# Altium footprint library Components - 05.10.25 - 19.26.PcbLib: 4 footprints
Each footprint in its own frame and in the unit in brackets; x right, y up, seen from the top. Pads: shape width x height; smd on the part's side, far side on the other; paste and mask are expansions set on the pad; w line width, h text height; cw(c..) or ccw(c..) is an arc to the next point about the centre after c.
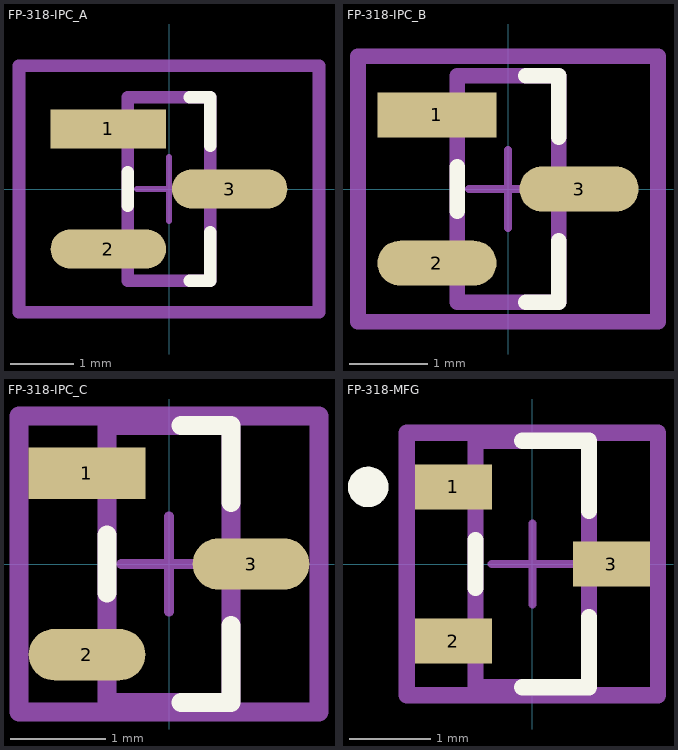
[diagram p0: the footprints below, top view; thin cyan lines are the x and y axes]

## FP-318-IPC_A [mm]
pads (3):
  rect 1.824x0.618 smd paste+0 mask+0: 1(-0.96,0.95)
  rrect100% 1.824x0.618 smd paste+0 mask+0: 2(-0.96,-0.95) 3(0.96,0)
Top Overlay:
  lines w0.2: -0.65,-0.266 -0.65,0.266 ; 0.327,-1.45 0.65,-1.45 0.65,-0.684 ; 0.327,1.45 0.65,1.45 0.65,0.684
Top Assembly:
  lines w0.2: -2.372,-1.95 2.372,-1.95 2.372,1.95 -2.372,1.95 -2.372,-1.95
  text ".Designator" at 0,0 h1
Top 3D Body:
  lines w0.2: -0.65,-1.45 0.65,-1.45 0.65,1.45 -0.65,1.45 -0.65,-1.45
Top Courtyard:
  lines w0.2: -2.372,-1.95 2.372,-1.95 2.372,1.95 -2.372,1.95 -2.372,-1.95
Top Component Center:
  lines w0.1: -0.5,0 0.5,0 ; 0,-0.5 0,0.5
3D body "Trans_onsemi_MMBT5179_eec.STEP": height 0.25, standoff 0, extent -2.372,-1.95 2.372,1.95

## FP-318-IPC_B [mm]
pads (3):
  rect 1.524x0.578 smd paste+0 mask+0: 1(-0.91,0.95)
  rrect100% 1.524x0.578 smd paste+0 mask+0: 2(-0.91,-0.95) 3(0.91,0)
Top Overlay:
  lines w0.2: -0.65,-0.286 -0.65,0.286 ; 0.227,-1.45 0.65,-1.45 0.65,-0.664 ; 0.227,1.45 0.65,1.45 0.65,0.664
Top Assembly:
  lines w0.2: -1.922,-1.7 1.922,-1.7 1.922,1.7 -1.922,1.7 -1.922,-1.7
  text ".Designator" at 0,0 h1
Top 3D Body:
  lines w0.2: -0.65,-1.45 0.65,-1.45 0.65,1.45 -0.65,1.45 -0.65,-1.45
Top Courtyard:
  lines w0.2: -1.922,-1.7 1.922,-1.7 1.922,1.7 -1.922,1.7 -1.922,-1.7
Top Component Center:
  lines w0.1: -0.5,0 0.5,0 ; 0,-0.5 0,0.5
3D body "Trans_onsemi_MMBT5179_eec.STEP": height 0.25, standoff 0, extent -1.922,-1.7 1.922,1.7

## FP-318-IPC_C [mm]
pads (3):
  rect 1.224x0.538 smd paste+0 mask+0: 1(-0.86,0.95)
  rrect100% 1.224x0.538 smd paste+0 mask+0: 2(-0.86,-0.95) 3(0.86,0)
Top Overlay:
  lines w0.2: -0.65,-0.306 -0.65,0.306 ; 0.127,-1.45 0.65,-1.45 0.65,-0.644 ; 0.127,1.45 0.65,1.45 0.65,0.644
Top Assembly:
  lines w0.2: -1.572,-1.55 1.572,-1.55 1.572,1.55 -1.572,1.55 -1.572,-1.55
  text ".Designator" at 0,0 h1
Top 3D Body:
  lines w0.2: -0.65,-1.45 0.65,-1.45 0.65,1.45 -0.65,1.45 -0.65,-1.45
Top Courtyard:
  lines w0.2: -1.572,-1.55 1.572,-1.55 1.572,1.55 -1.572,1.55 -1.572,-1.55
Top Component Center:
  lines w0.1: -0.5,0 0.5,0 ; 0,-0.5 0,0.5
3D body "Trans_onsemi_MMBT5179_eec.STEP": height 0.25, standoff 0, extent -1.572,-1.55 1.572,1.55

## FP-318-MFG [mm]
pads (3):
  rect 0.95x0.56 smd paste+0 mask+0: 1(-0.975,0.95) 2(-0.975,-0.95) 3(0.975,0)
Top Overlay:
  circle w0.25: c-2.025,0.95 r0.125
  lines w0.2: -0.7,-0.295 -0.7,0.295 ; -0.125,-1.52 0.7,-1.52 0.7,-0.655 ; -0.125,1.52 0.7,1.52 0.7,0.655
Top Assembly:
  lines w0.2: -1.55,-1.62 1.55,-1.62 1.55,1.62 -1.55,1.62 -1.55,-1.62
  text ".Designator" at 0,0.188 h1
Top 3D Body:
  lines w0.2: -0.7,-1.52 0.7,-1.52 0.7,1.52 -0.7,1.52 -0.7,-1.52
Top Courtyard:
  lines w0.2: -1.55,-1.62 1.55,-1.62 1.55,1.62 -1.55,1.62 -1.55,-1.62
Top Component Center:
  lines w0.1: -0.5,0 0.5,0 ; 0,-0.5 0,0.5
3D body "Trans_onsemi_MMBT5179_eec.STEP": height 0.25, standoff 0, extent -1.55,-1.62 1.55,1.62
